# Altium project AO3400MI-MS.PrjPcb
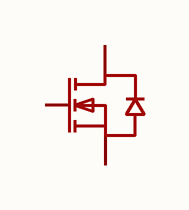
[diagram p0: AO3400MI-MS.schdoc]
1 sheet, 1 parts. Net scope: global (net labels, ports and power ports of the same name join across sheets).

## Sheet AO3400MI-MS.schdoc
size 127 x 101 mm

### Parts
Q?  ao3400mi-ms  [SOT-23-3_L2.9-W1.3-P1.90-LS2.4-BR]  (value not drawn)

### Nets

Not connected (* = marked no-connect by the designer): Q? 1(G) 2(S) 3(D)

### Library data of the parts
Q? = ao3400mi-ms: 数量:1个N沟道;漏源电压(Vdss):30V;连续漏极电流(Id):5.8A;导通电阻(RDS(on)):20mΩ@10V;耗散功率(Pd):1.5W;阈值电压(Vgs(th)):900mV;; Manufacturer: MSKSEMI(美森科); AddInBom: yes; ModelId: c62791f0466c4ae2a892c056b845b0ca; ModelName: SOT-23-3P_L2.9-W1.3-H1.0-LS2.4-P0.95; ModelTransform: 98.425,114.173,0,180,0,0,0.0005,-0.0005,0; Number: 1个N沟道; Drain to Source Voltage: 30V; Current - Continuous Drain(Id): 5.8A; Pd - Power Dissipation: 1.5W; Gate Threshold Voltage (Vgs(th)): 900mV; Gate Charge(Qg): 4.8nC@4.5V; Input Capacitance(Ciss): 602pF; Reverse Transfer Capacitance (Crss@Vds): 42pF; Type: N沟道; Output Capacitance(Coss): 56pF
